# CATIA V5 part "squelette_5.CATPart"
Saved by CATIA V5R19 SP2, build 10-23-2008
Part number: squelette_5
Publications: "Point.1", "Point.2", "Droite.1", "Droite.2"
Bounding box of the stored display mesh (mm): x -10 to 10, y 0 to 28, z -3 to 3
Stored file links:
  M:\EU_thinkMotion\IAO_2010\iao\IAO_MMS_Groupe2\IAO_MMS_Groupe2\sdubois\sdubois\sdubois\IAO_mecanisme\squelette_5.CATPart
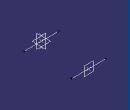
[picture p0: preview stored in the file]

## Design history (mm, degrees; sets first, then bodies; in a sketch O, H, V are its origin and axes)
Set1
  Point1: (0, 0, 0)
  Point2: (0, 28, 0)
  Line1: type PtDir, RefPoint Point1, Direction yz-plane, Start -10, End 10
  Line2: type PtDir, RefPoint Point2, Direction yz-plane, Start -10, End 10
  Plane1: type OffsetPt, RefPlane zx-plane, RefPoint Point2
  Point3: (0, 0, 3)
  Point4: (0, 0, -3)
Body1 (main body)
